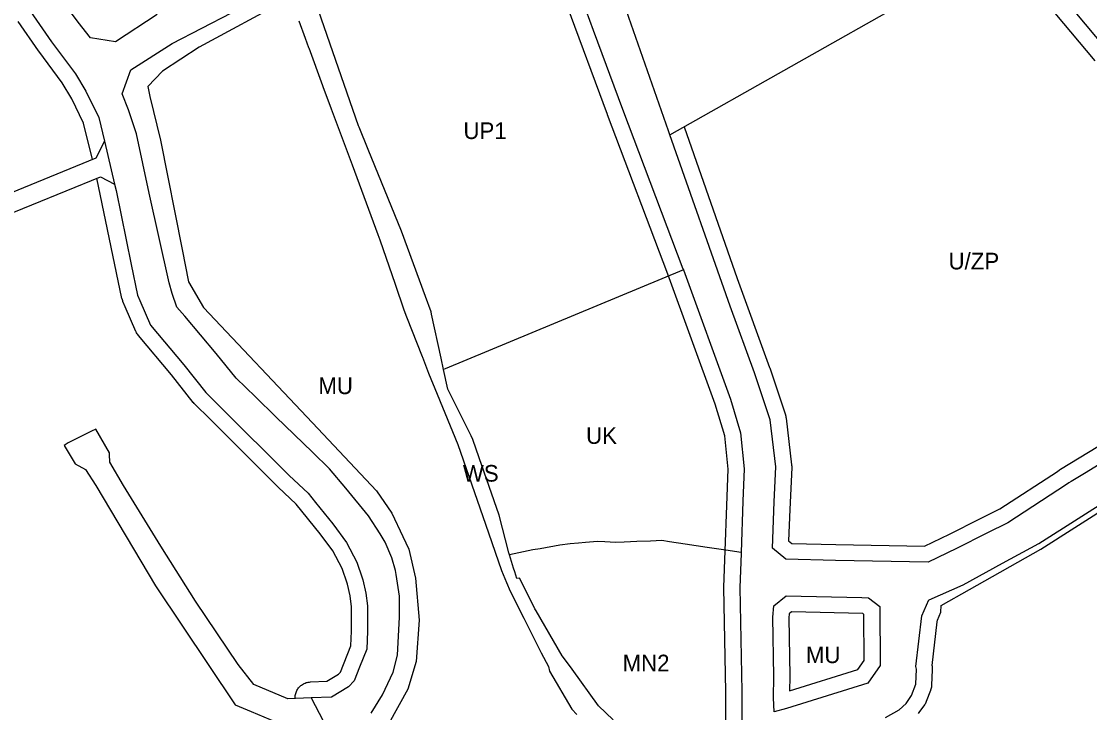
# Model space of a CAD drawing. Extents: x 7435758 to 7439981, y 5550649 to 5554049.
# Drawn here: x 7437108.2 to 7437442.5, y 5551743.2 to 5551959.4 of the extents above; entities that cross this region are included whole.
import ezdxf

# ---------------------------------------------------------------- set-up
doc = ezdxf.new("R2010")
doc.units = 0
for name, color, linetype in [('linie_rozgraniczające', 7, 'Continuous'), ('linie_zabudowy_nieprzekraczalne', 7, 'Continuous'), ('oznaczenia_przeznaczen', 7, 'Continuous')]:
    doc.layers.add(name, color=color, linetype=linetype)

msp = doc.modelspace()

# ---------------------------------------------------------------- linework, layer by layer
at = {"layer": 'linie_rozgraniczające'}
for p, q in [((7437310.72, 5551925.14), (7437288.06, 5551989.83)), ((7437311.16, 5551923.91), (7437419.08, 5551984.95)), ((7437419.08, 5551984.95), (7437448.05, 5551950.24)), ((7437125.96, 5551959.19), (7437119.37, 5551968.13)), ((7437155.38, 5551952.51), (7437187.73, 5551969.28)), ((7437283.67, 5551966.04), (7437287.17, 5551956.64)), ((7437111.09, 5551962.57), (7437117.68, 5551953.08)), ((7437150.73, 5551961.56), (7437137.72, 5551953.08)), ((7437213.75, 5551926.75), (7437201.22, 5551962.82)), ((7437129.81, 5551954.29), (7437125.96, 5551959.19)), ((7437195.02, 5551959.58), (7437196.99, 5551954.22)), ((7437137.72, 5551953.08), (7437129.81, 5551954.29)), ((7437196.99, 5551954.22), (7437198.07, 5551951.28)), ((7437287.17, 5551956.64), (7437296.34, 5551932)), ((7437117.68, 5551953.08), (7437125.18, 5551942.98)), ((7437142.48, 5551944.32), (7437155.38, 5551952.51)), ((7437198.07, 5551951.28), (7437198.12, 5551951.14)), ((7437198.12, 5551951.14), (7437202.44, 5551939.38)), ((7437139.79, 5551936.79), (7437142.48, 5551944.32)), ((7437125.18, 5551942.98), (7437128.43, 5551937.61)), ((7437128.43, 5551937.61), (7437132.45, 5551929.33)), ((7437141.77, 5551931.79), (7437139.79, 5551936.79)), ((7437202.44, 5551939.38), (7437202.54, 5551939.1)), ((7437202.54, 5551939.1), (7437205.16, 5551932.09)), ((7437144.24, 5551924.2), (7437141.77, 5551931.79)), ((7437205.16, 5551932.09), (7437210.46, 5551917.9)), ((7437296.34, 5551932), (7437315.2, 5551882.06)), ((7437132.45, 5551929.33), (7437134.25, 5551921.99)), ((7437213.89, 5551926.34), (7437213.75, 5551926.75)), ((7437148.18, 5551905.7), (7437144.24, 5551924.2)), ((7437216.75, 5551919.34), (7437213.89, 5551926.34)), ((7437311.16, 5551923.91), (7437310.72, 5551925.14)), ((7437330, 5551870.35), (7437311.16, 5551923.91)), ((7437134.25, 5551921.99), (7437131.52, 5551916.61)), ((7437134.25, 5551921.99), (7437137.41, 5551908.47)), ((7437210.46, 5551917.9), (7437211.71, 5551914.57)), ((7437227.16, 5551893.83), (7437216.75, 5551919.34)), ((7437131.52, 5551916.61), (7437060.3, 5551887.61)), ((7437211.71, 5551914.57), (7437219.76, 5551892.77)), ((7437033.37, 5551870.27), (7437132.96, 5551910.8)), ((7437132.96, 5551910.8), (7437137.41, 5551908.47)), ((7437137.41, 5551908.47), (7437137.86, 5551906.52)), ((7437137.86, 5551906.52), (7437142.62, 5551883.4)), ((7437154.48, 5551877.64), (7437148.18, 5551905.7)), ((7437234.67, 5551873.33), (7437227.16, 5551893.83)), ((7437219.76, 5551892.77), (7437220.38, 5551891.08)), ((7437220.38, 5551891.08), (7437225.13, 5551877.21)), ((7437142.62, 5551883.4), (7437144.61, 5551873.76)), ((7437315.34, 5551881.67), (7437240.79, 5551850.74)), ((7437315.2, 5551882.06), (7437315.34, 5551881.67)), ((7437315.34, 5551881.67), (7437330.07, 5551841.21)), ((7437155.41, 5551874.29), (7437154.48, 5551877.64)), ((7437225.13, 5551877.21), (7437227.86, 5551869.21)), ((7437144.61, 5551873.76), (7437145.3, 5551872.11)), ((7437156.88, 5551870), (7437155.41, 5551874.29)), ((7437236.41, 5551868.57), (7437234.67, 5551873.33)), ((7437145.3, 5551872.11), (7437148.67, 5551864.39)), ((7437159.42, 5551867.15), (7437156.88, 5551870)), ((7437337.64, 5551849.43), (7437330, 5551870.35)), ((7437169.21, 5551855.54), (7437159.42, 5551867.15)), ((7437227.86, 5551869.21), (7437228.74, 5551866.96)), ((7437228.74, 5551866.96), (7437233.59, 5551854.63)), ((7437236.58, 5551867.8), (7437236.41, 5551868.57)), ((7437239.55, 5551854.01), (7437236.58, 5551867.8)), ((7437148.67, 5551864.39), (7437159.03, 5551851.97)), ((7437175.45, 5551847.79), (7437169.21, 5551855.54)), ((7437233.59, 5551854.63), (7437233.69, 5551854.36)), ((7437233.69, 5551854.36), (7437233.71, 5551854.32)), ((7437233.71, 5551854.32), (7437235.65, 5551849.39)), ((7437240.3, 5551850.54), (7437239.55, 5551854.01)), ((7437159.03, 5551851.97), (7437165.9, 5551843.34)), ((7437240.79, 5551850.74), (7437240.3, 5551850.54)), ((7437241.63, 5551844.38), (7437240.3, 5551850.54)), ((7437181.49, 5551841.92), (7437175.45, 5551847.79)), ((7437235.65, 5551849.39), (7437238.33, 5551842.82)), ((7437342.53, 5551834.72), (7437337.64, 5551849.43)), ((7437165.9, 5551843.34), (7437170.79, 5551838.52)), ((7437248.93, 5551829.73), (7437241.63, 5551844.38)), ((7437187.89, 5551835.71), (7437181.49, 5551841.92)), ((7437238.33, 5551842.82), (7437244.76, 5551827.03)), ((7437330.07, 5551841.21), (7437333.2, 5551830.73)), ((7437170.79, 5551838.52), (7437192.04, 5551817.35)), ((7437199.27, 5551824.66), (7437187.89, 5551835.71)), ((7437344.25, 5551820.11), (7437342.53, 5551834.72)), ((7437426.54, 5551796.11), (7437485.44, 5551833.4)), ((7437470.98, 5551836.32), (7437440.82, 5551817.99)), ((7437130.2, 5551831.19), (7437122.83, 5551827.52)), ((7437131.58, 5551831.83), (7437130.2, 5551831.19)), ((7437135.84, 5551824.4), (7437131.58, 5551831.83)), ((7437333.2, 5551830.73), (7437334.34, 5551819.48)), ((7437122.83, 5551827.52), (7437121.57, 5551826.75)), ((7437121.57, 5551826.75), (7437125.09, 5551820.97)), ((7437244.76, 5551827.03), (7437253.4, 5551802.16)), ((7437249.47, 5551828.65), (7437248.93, 5551829.73)), ((7437251.48, 5551822.89), (7437249.47, 5551828.65)), ((7437135.85, 5551823.92), (7437135.84, 5551824.4)), ((7437135.91, 5551821.54), (7437135.85, 5551823.92)), ((7437204.65, 5551819.43), (7437199.27, 5551824.66)), ((7437125.09, 5551820.97), (7437128.27, 5551819.24)), ((7437140.23, 5551814.22), (7437135.91, 5551821.54)), ((7437257.73, 5551804.97), (7437251.48, 5551822.89)), ((7437343.79, 5551809.08), (7437344.25, 5551820.11)), ((7437128.27, 5551819.24), (7437131.54, 5551814.26)), ((7437192.04, 5551817.35), (7437197.92, 5551811.81)), ((7437209.79, 5551813.35), (7437204.65, 5551819.43)), ((7437334.34, 5551819.48), (7437333.98, 5551809.36)), ((7437440.82, 5551817.99), (7437436.65, 5551815.45)), ((7437131.54, 5551814.26), (7437150.19, 5551782.86)), ((7437151.89, 5551795.25), (7437140.23, 5551814.22)), ((7437216.85, 5551804.72), (7437209.79, 5551813.35)), ((7437435.2, 5551814.51), (7437416.9, 5551802.57)), ((7437435.93, 5551815.02), (7437435.2, 5551814.51)), ((7437436.65, 5551815.45), (7437435.93, 5551815.02)), ((7437197.92, 5551811.81), (7437200.23, 5551808.94)), ((7437200.23, 5551808.94), (7437205.65, 5551802.2)), ((7437333.98, 5551809.36), (7437333.41, 5551793.26)), ((7437343.19, 5551794.6), (7437343.79, 5551809.08)), ((7437220.51, 5551799.11), (7437216.85, 5551804.72)), ((7437260.73, 5551793.18), (7437257.73, 5551804.97)), ((7437205.65, 5551802.2), (7437209.96, 5551796.43)), ((7437253.4, 5551802.16), (7437258.46, 5551787.58)), ((7437416.9, 5551802.57), (7437410.33, 5551799.27)), ((7437209.96, 5551796.43), (7437213.16, 5551790.18)), ((7437222.04, 5551796.45), (7437220.51, 5551799.11)), ((7437224.17, 5551791.6), (7437222.04, 5551796.45)), ((7437284.72, 5551796.42), (7437282.57, 5551796.22)), ((7437288.52, 5551796.69), (7437284.72, 5551796.42)), ((7437290.81, 5551796.62), (7437288.52, 5551796.69)), ((7437294.07, 5551796.37), (7437290.81, 5551796.62)), ((7437296.8, 5551796.48), (7437294.07, 5551796.37)), ((7437300.84, 5551796.65), (7437296.8, 5551796.48)), ((7437305.05, 5551796.82), (7437300.84, 5551796.65)), ((7437308.64, 5551796.97), (7437305.05, 5551796.82)), ((7437311.01, 5551796.61), (7437308.64, 5551796.97)), ((7437315.87, 5551795.89), (7437311.01, 5551796.61)), ((7437410.33, 5551799.27), (7437400.82, 5551794.5)), ((7437162.7, 5551778.05), (7437151.89, 5551795.25)), ((7437260.91, 5551792.5), (7437260.73, 5551793.18)), ((7437268.28, 5551794.06), (7437260.91, 5551792.5)), ((7437270.56, 5551794.45), (7437268.28, 5551794.06)), ((7437276.72, 5551795.5), (7437270.56, 5551794.45)), ((7437279.95, 5551795.97), (7437276.72, 5551795.5)), ((7437282.57, 5551796.22), (7437279.95, 5551795.97)), ((7437322.76, 5551794.85), (7437315.87, 5551795.89)), ((7437328.64, 5551793.97), (7437322.76, 5551794.85)), ((7437333.41, 5551793.26), (7437328.64, 5551793.97)), ((7437333.41, 5551793.26), (7437333.4, 5551792.92)), ((7437347.45, 5551791.15), (7437343.19, 5551794.6)), ((7437400.82, 5551794.5), (7437391.92, 5551790.26)), ((7437415.15, 5551789.89), (7437426.54, 5551796.11)), ((7437213.16, 5551790.18), (7437214.87, 5551785.32)), ((7437225.33, 5551787.62), (7437224.17, 5551791.6)), ((7437262.2, 5551788.39), (7437260.91, 5551792.5)), ((7437333.4, 5551792.92), (7437333.02, 5551782.27)), ((7437362.95, 5551790.73), (7437347.45, 5551791.15)), ((7437391.92, 5551790.26), (7437362.95, 5551790.73)), ((7437402.89, 5551783.18), (7437415.15, 5551789.89)), ((7437225.51, 5551786.35), (7437225.33, 5551787.62)), ((7437226.5, 5551779.6), (7437225.51, 5551786.35)), ((7437258.46, 5551787.58), (7437260.02, 5551783.82)), ((7437262.58, 5551787.16), (7437262.2, 5551788.39)), ((7437263.23, 5551785.09), (7437262.58, 5551787.16)), ((7437214.87, 5551785.32), (7437215.1, 5551784.68)), ((7437215.1, 5551784.68), (7437216.03, 5551780.49)), ((7437260.02, 5551783.82), (7437261.13, 5551781.16)), ((7437264.08, 5551785.25), (7437263.23, 5551785.09)), ((7437268.65, 5551776.1), (7437264.08, 5551785.25)), ((7437392.24, 5551778.46), (7437402.89, 5551783.18)), ((7437150.19, 5551782.86), (7437175.17, 5551745.63)), ((7437216.03, 5551780.49), (7437216.48, 5551776.54)), ((7437261.13, 5551781.16), (7437265.41, 5551772.68)), ((7437333.02, 5551782.27), (7437333.66, 5551749.77)), ((7437343.65, 5551776.57), (7437347.49, 5551779.72)), ((7437347.49, 5551779.72), (7437371.21, 5551779.19)), ((7437176.08, 5551758.24), (7437162.7, 5551778.05)), ((7437216.48, 5551776.54), (7437216.48, 5551768.59)), ((7437226.57, 5551772.99), (7437226.5, 5551779.6)), ((7437343.34, 5551772.98), (7437343.65, 5551776.57)), ((7437371.21, 5551779.19), (7437373.26, 5551779.12)), ((7437373.26, 5551779.12), (7437376.85, 5551776.36)), ((7437376.85, 5551776.36), (7437376.93, 5551757.87)), ((7437389.94, 5551773.42), (7437392.15, 5551778.46)), ((7437392.15, 5551778.46), (7437392.24, 5551778.46)), ((7437225.88, 5551761.1), (7437226.57, 5551772.99)), ((7437268.92, 5551775.64), (7437268.65, 5551776.1)), ((7437269.29, 5551774.98), (7437268.92, 5551775.64)), ((7437277.44, 5551760.89), (7437269.29, 5551774.98)), ((7437343.64, 5551754.47), (7437343.34, 5551772.98)), ((7437388.11, 5551757.56), (7437389.94, 5551773.42)), ((7437265.41, 5551772.68), (7437266.06, 5551771.41)), ((7437266.06, 5551771.41), (7437270.88, 5551761.88)), ((7437216.48, 5551768.59), (7437216.29, 5551763.03)), ((7437216.29, 5551763.03), (7437214.07, 5551757.39)), ((7437224.57, 5551755.83), (7437225.88, 5551761.1)), ((7437270.88, 5551761.88), (7437273.13, 5551757.57)), ((7437278.17, 5551759.94), (7437277.44, 5551760.89)), ((7437280.58, 5551756.75), (7437278.17, 5551759.94)), ((7437181, 5551751.96), (7437176.08, 5551758.24)), ((7437214.07, 5551757.39), (7437212.38, 5551753.1)), ((7437273.13, 5551757.57), (7437273.42, 5551756.12)), ((7437288.8, 5551745.24), (7437280.58, 5551756.75)), ((7437376.93, 5551757.87), (7437373.07, 5551752.36)), ((7437388.32, 5551756.77), (7437388.11, 5551757.56)), ((7437388.11, 5551752.01), (7437388.32, 5551756.77)), ((7437212.38, 5551753.1), (7437210.63, 5551751.22)), ((7437221.24, 5551748.69), (7437224.57, 5551755.83)), ((7437273.42, 5551756.12), (7437280.47, 5551744.21)), ((7437343.5, 5551747.76), (7437343.64, 5551754.47)), ((7437191.56, 5551747.46), (7437181, 5551751.96)), ((7437210.63, 5551751.22), (7437205.28, 5551748.01)), ((7437333.66, 5551749.77), (7437333.45, 5551705.87)), ((7437373.07, 5551752.36), (7437347.6, 5551744.41)), ((7437386.77, 5551748.49), (7437388.11, 5551752.01)), ((7437198.86, 5551747.75), (7437191.56, 5551747.46)), ((7437205.28, 5551748.01), (7437198.86, 5551747.75)), ((7437198.86, 5551747.75), (7437206.28, 5551733.7)), ((7437205.28, 5551748.01), (7437205.28, 5551748.01)), ((7437205.28, 5551748.01), (7437205.28, 5551748.01)), ((7437217.69, 5551742.95), (7437221.24, 5551748.69)), ((7437343.71, 5551743.35), (7437343.5, 5551747.76)), ((7437385.05, 5551746.03), (7437386.77, 5551748.49)), ((7437175.17, 5551745.63), (7437180.18, 5551743.49)), ((7437180.18, 5551743.49), (7437192.05, 5551738.53)), ((7437280.47, 5551744.21), (7437281.97, 5551742.54)), ((7437293.36, 5551740.92), (7437288.8, 5551745.24)), ((7437347.6, 5551744.41), (7437343.71, 5551743.35)), ((7437378.55, 5551741.64), (7437382.91, 5551744.04)), ((7437382.91, 5551744.04), (7437385.05, 5551746.03))]:
    msp.add_line(p, q, dxfattribs=at)
at = {"layer": 'linie_zabudowy_nieprzekraczalne'}
for points in [[(7437327.25, 5551677.18), (7437328.56, 5551675.97), (7437328.36, 5551687.67), (7437328.36, 5551687.78), (7437328.66, 5551749.73), (7437328.02, 5551782.17), (7437328.02, 5551782.39), (7437328.03, 5551782.45), (7437329.33, 5551819.31), (7437328.28, 5551829.75), (7437325.32, 5551839.64), (7437310.51, 5551880.32), (7437291.66, 5551930.23), (7437291.66, 5551930.26), (7437278.98, 5551964.3), (7437278.97, 5551964.34), (7437266.89, 5551997.74), (7437262.43, 5551995.85), (7437262.4, 5551995.84), (7437197.61, 5551968.8)], [(7437444.22, 5551947.04), (7437414.28, 5551982.9)], [(7437191.25, 5551966.29), (7437163.85, 5551951.36), (7437152.38, 5551943.89), (7437147.78, 5551939.1), (7437148.4, 5551935.88), (7437151.79, 5551922.29), (7437158.55, 5551888.1), (7437160.55, 5551877.97), (7437165.17, 5551869.95), (7437199.31, 5551833.78), (7437219.36, 5551812.53), (7437224.19, 5551805.57), (7437227.61, 5551798.26), (7437229.46, 5551794.3), (7437231.53, 5551785.24), (7437232.7, 5551772.13), (7437231.76, 5551759.2), (7437229.18, 5551750.51), (7437223.17, 5551739.77)], [(7437130.53, 5551916.2), (7437127.72, 5551927.62), (7437124.03, 5551935.22), (7437121.03, 5551940.19), (7437113.66, 5551950.1), (7437113.64, 5551950.14), (7437113.57, 5551950.23), (7437107.2, 5551959.4)], [(7437315.57, 5551926.41), (7437332.15, 5551879.01), (7437332.17, 5551878.96), (7437342.33, 5551851.14), (7437342.38, 5551851), (7437347.27, 5551836.29), (7437347.3, 5551836.21), (7437347.39, 5551835.89), (7437347.45, 5551835.57), (7437347.49, 5551835.3), (7437349.21, 5551820.69), (7437349.22, 5551820.63), (7437349.24, 5551820.31), (7437349.25, 5551819.98), (7437349.24, 5551819.9), (7437348.7, 5551806.67), (7437348.29, 5551796.91), (7437349.28, 5551796.1), (7437363.06, 5551795.73), (7437390.83, 5551795.28), (7437398.62, 5551798.99), (7437408.09, 5551803.74), (7437414.4, 5551806.91), (7437432.41, 5551818.65), (7437433.08, 5551819.12), (7437433.26, 5551819.24), (7437433.34, 5551819.29), (7437468.39, 5551840.59)], [(7437193.86, 5551747.55), (7437193.86, 5551747.88), (7437193.88, 5551748.2), (7437193.92, 5551748.53), (7437193.98, 5551748.85), (7437194.06, 5551749.17), (7437194.16, 5551749.48), (7437194.29, 5551749.78), (7437194.43, 5551750.08), (7437194.59, 5551750.36), (7437194.77, 5551750.63), (7437194.97, 5551750.9), (7437195.18, 5551751.14), (7437195.41, 5551751.38), (7437195.65, 5551751.59), (7437195.91, 5551751.79), (7437196.18, 5551751.98), (7437196.47, 5551752.14), (7437196.76, 5551752.29), (7437197.06, 5551752.42), (7437197.37, 5551752.53), (7437197.68, 5551752.61), (7437198, 5551752.68), (7437198.33, 5551752.73), (7437198.65, 5551752.75), (7437203.81, 5551752.96), (7437207.45, 5551755.15), (7437208.08, 5551755.82), (7437211.32, 5551764.06), (7437211.48, 5551768.68), (7437211.48, 5551776.26), (7437211.09, 5551779.66), (7437210.28, 5551783.3), (7437210.15, 5551783.66), (7437208.55, 5551788.2), (7437205.7, 5551793.77), (7437201.7, 5551799.14), (7437194.24, 5551808.41), (7437188.61, 5551813.71), (7437188.51, 5551813.81), (7437167.28, 5551834.96), (7437162.39, 5551839.78), (7437162.28, 5551839.9), (7437162.06, 5551840.14), (7437161.99, 5551840.23), (7437155.16, 5551848.81), (7437144.83, 5551861.18), (7437144.63, 5551861.44), (7437144.45, 5551861.71), (7437144.28, 5551862), (7437144.13, 5551862.29), (7437144.09, 5551862.39), (7437140.72, 5551870.11), (7437140.7, 5551870.17), (7437140, 5551871.82), (7437139.95, 5551871.96), (7437139.84, 5551872.27), (7437139.75, 5551872.58), (7437139.71, 5551872.75), (7437131.85, 5551910.35)], [(7437388.94, 5551742.88), (7437389.14, 5551743.15), (7437389.15, 5551743.17), (7437390.87, 5551745.63), (7437391.03, 5551745.88), (7437391.19, 5551746.16), (7437391.34, 5551746.46), (7437391.44, 5551746.71), (7437392.78, 5551750.22), (7437392.8, 5551750.28), (7437392.9, 5551750.59), (7437392.99, 5551750.91), (7437393.05, 5551751.23), (7437393.09, 5551751.55), (7437393.1, 5551751.78), (7437393.32, 5551756.55), (7437393.32, 5551756.65), (7437393.32, 5551756.97), (7437393.29, 5551757.3), (7437393.25, 5551757.62), (7437393.18, 5551757.93), (7437393.19, 5551757.94), (7437394.76, 5551771.61), (7437394.82, 5551772.1), (7437395.93, 5551774.63), (7437395.97, 5551776.64), (7437404.9, 5551781.71), (7437427.15, 5551794.29), (7437449.65, 5551808.57)], [(7437348.54, 5551749.94), (7437369.95, 5551756.62), (7437371.93, 5551759.44), (7437371.86, 5551773.89), (7437371.49, 5551774.18), (7437349.23, 5551774.68), (7437348.45, 5551774.04), (7437348.34, 5551772.8), (7437348.64, 5551754.55), (7437348.64, 5551754.39), (7437348.64, 5551754.36), (7437348.54, 5551749.94)]]:
    msp.add_lwpolyline(points, dxfattribs=at)

# ---------------------------------------------------------------- texts
at = {"layer": 'oznaczenia_przeznaczen'}
for s, p in [('UP1', (7437246.54, 5551922.63)), ('U/ZP', (7437398.32, 5551881.83)), ('MU', (7437201.15, 5551842.81)), ('UK', (7437284.91, 5551827.25)), ('WS', (7437246.36, 5551815.43)), ('MU', (7437353.68, 5551758.64)), ('MN2', (7437296.34, 5551756.08))]:
    msp.add_text(s, height=5.2, dxfattribs=at).set_placement(p)

doc.saveas('drawing.dxf')
